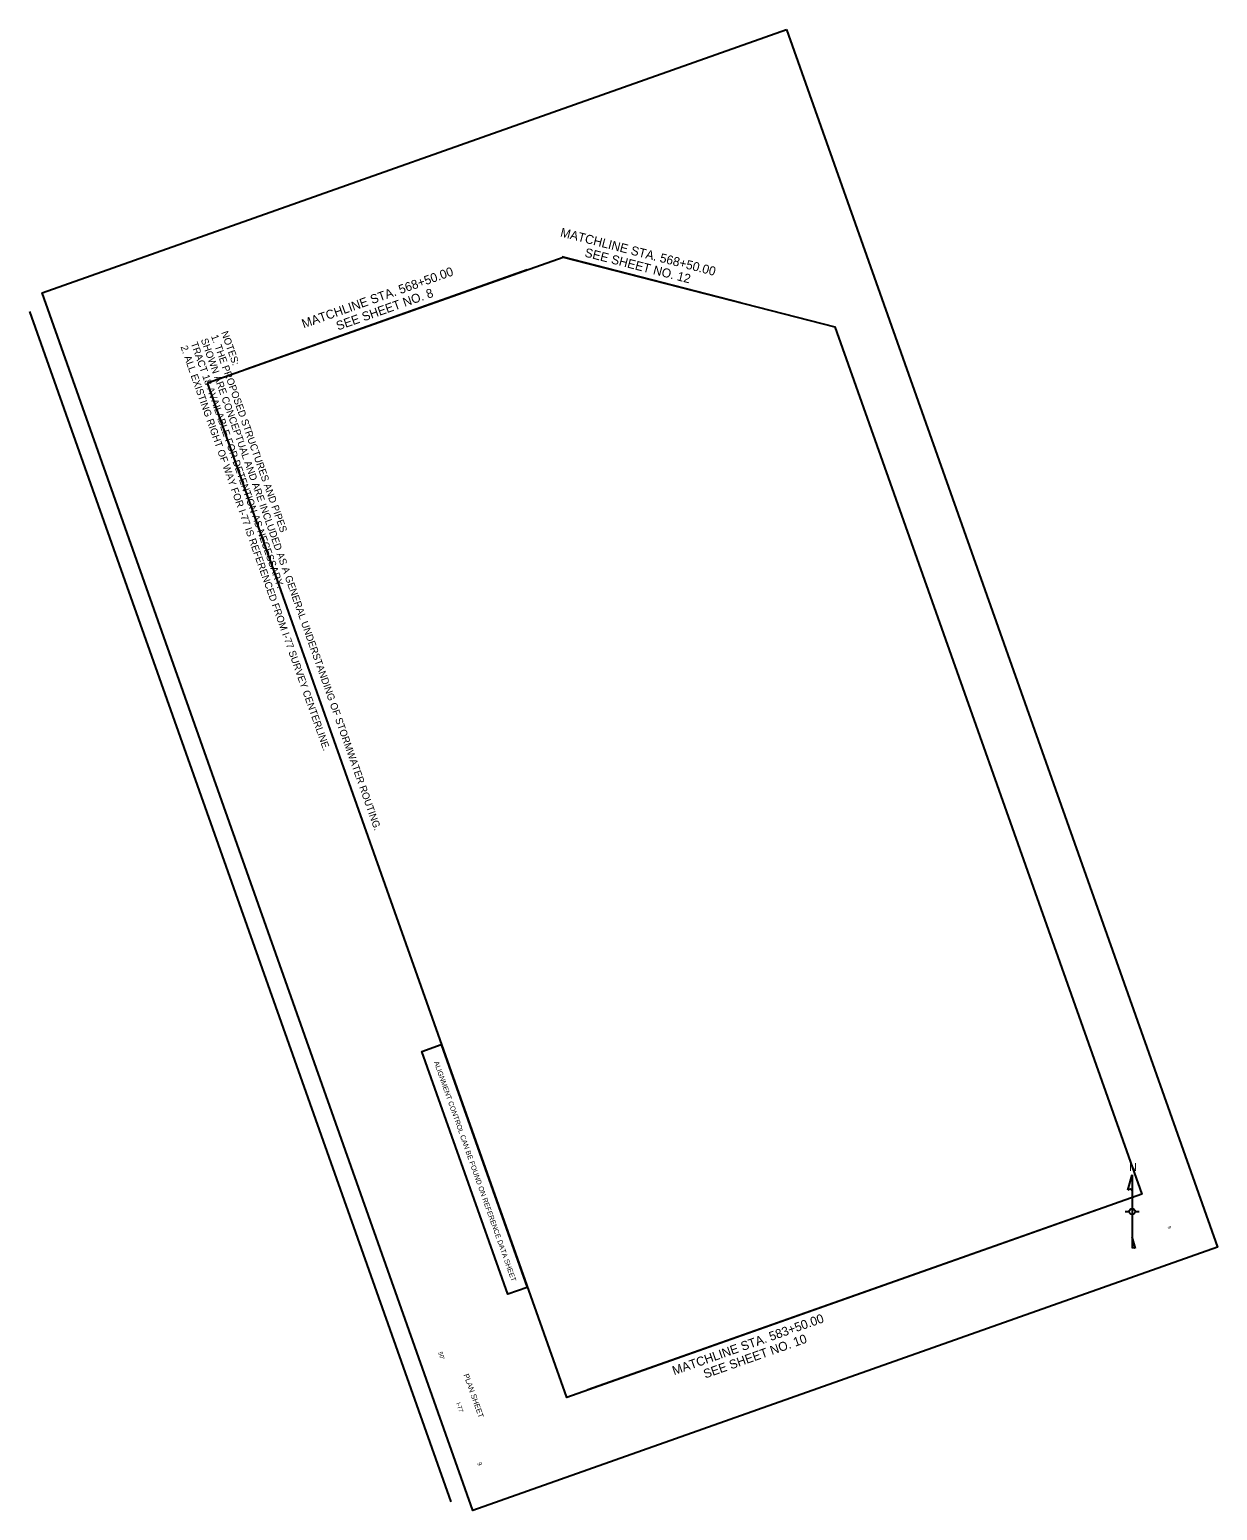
# Model space of a CAD drawing. Extents: x 2005690 to 2007344, y 1134707 to 1136771.
import ezdxf

# ---------------------------------------------------------------- set-up
doc = ezdxf.new("R2010")
doc.units = 0
for name, color, linetype in [('North Arrow', 7, 'Continuous'), ('RD_SHT_IplotShp', 7, 'Continuous'), ('RD_SHT_MatchLine', 7, 'Continuous'), ('RD_SHT_Misc1', 7, 'Continuous'), ('RD_SHT_ShtClip', 7, 'Continuous'), ('RD_SHT_TX', 7, 'Continuous')]:
    doc.layers.add(name, color=color, linetype=linetype)

msp = doc.modelspace()

# ---------------------------------------------------------------- linework, layer by layer
at = {"layer": 'North Arrow'}
for p, q in [((2007219.6, 1135153.3), (2007225.5, 1135174.3)), ((2007225.5, 1135174.3), (2007225.5, 1135152.2)), ((2007225.5, 1135174.3), (2007225.5, 1135072.1)), ((2007215.8, 1135123.2), (2007221.5, 1135123.2)), ((2007229.5, 1135123.2), (2007235.2, 1135123.2)), ((2007225.5, 1135087.9), (2007225.5, 1135072.1)), ((2007230.1, 1135071.8), (2007225.5, 1135087.9))]:
    msp.add_line(p, q, dxfattribs=at)
msp.add_circle((2007225.5, 1135123.2), 4.02, dxfattribs=at)
for centre, radius, start, end in [((2007222.2, 1135150.8), 3.59, 22.3707, 136.1387), ((2007227.7, 1135069.6), 3.3, 43.3397, 130.5607)]:
    msp.add_arc(centre, radius, start, end, dxfattribs=at)
at = {"layer": 'RD_SHT_IplotShp'}
msp.add_lwpolyline([(2006743.9, 1136770.6), (2007344.2, 1135073.6), (2006307.2, 1134706.8), (2005706.9, 1136403.7)], close=True, dxfattribs=at)
at = {"layer": 'RD_SHT_MatchLine'}
for p, q in [((2006382.6, 1136435.7), (2005990.6, 1136297)), ((2006680.4, 1136389.9), (2006431.3, 1136453.8)), ((2007174.3, 1135124.7), (2006467.3, 1134874.6))]:
    msp.add_line(p, q, dxfattribs=at)
at = {"layer": 'RD_SHT_ShtClip'}
msp.add_lwpolyline([(2005937.5, 1136278.3), (2006432.7, 1136453.4), (2006811.5, 1136356.3), (2007239.1, 1135147.6), (2006437.8, 1134864.1)], close=True, dxfattribs=at)
at = {"layer": 'RD_SHT_TX'}
msp.add_line((2005689.5, 1136377.8), (2006276.5, 1134718.6), dxfattribs=at)
msp.add_lwpolyline([(2006262.8, 1135356), (2006382.6, 1135017.4), (2006355.8, 1135007.9), (2006236, 1135346.5)], close=True, dxfattribs=at)

# ---------------------------------------------------------------- texts
at = {"layer": 'North Arrow'}
msp.add_text('N', height=11.1, dxfattribs=at).set_placement((2007221.4, 1135179.8))
at = {"layer": 'RD_SHT_MatchLine'}
for s, rotation, p in [('MATCHLINE STA. 568+50.00', 345.6281, (2006428, 1136482.5)), ('SEE SHEET NO. 12', 345.6281, (2006461.9, 1136454.4)), ('MATCHLINE STA. 568+50.00', 19.482, (2006071.3, 1136354.2)), ('SEE SHEET NO. 8', 19.482, (2006119.2, 1136351.2)), ('MATCHLINE STA. 583+50.00', 19.482, (2006587.4, 1134895.1)), ('SEE SHEET NO. 10', 19.482, (2006630.8, 1134890.5))]:
    msp.add_text(s, height=12.5, rotation=rotation, dxfattribs=at).set_placement(p)
at = {"layer": 'RD_SHT_Misc1'}
for s, p in [('TRACT 18 AVAILABLE FOR DETENTION AS NECESSARY. ', (2005913.8, 1136333.4)), ('SHOWN ARE CONCEPTUAL AND ARE INCLUDED AS A GENERAL UNDERSTANDING OF STORMWATER ROUTING.  ', (2005927.9, 1136338.4)), ('1. THE PROPOSED STRUCTURES AND PIPES ', (2005942.1, 1136343.4)), ('NOTES:', (2005956.2, 1136348.4)), ('2. ALL EXISTING RIGHT OF WAY FOR I-77 IS REFERENCED FROM I-77 SURVEY CENTERLINE.', (2005899.6, 1136328.4))]:
    msp.add_text(s, height=10, rotation=289.482, dxfattribs=at).set_placement(p)
at = {"layer": 'RD_SHT_TX'}
for s, height, p in [('ALIGNMENT CONTROL CAN BE FOUND ON REFERENCE DATA SHEET', 7, (2006252.7, 1135331.4)), ('9', 4.5, (2007274.8, 1135102.1)), ("50'", 6, (2006258.6, 1134926.7)), ('PLAN SHEET', 7.5, (2006293.9, 1134895.7)), ('I-77', 6, (2006283.6, 1134856.1)), ('9', 6, (2006313, 1134772.8))]:
    msp.add_text(s, height=height, rotation=289.482, dxfattribs=at).set_placement(p)

doc.saveas('drawing.dxf')
